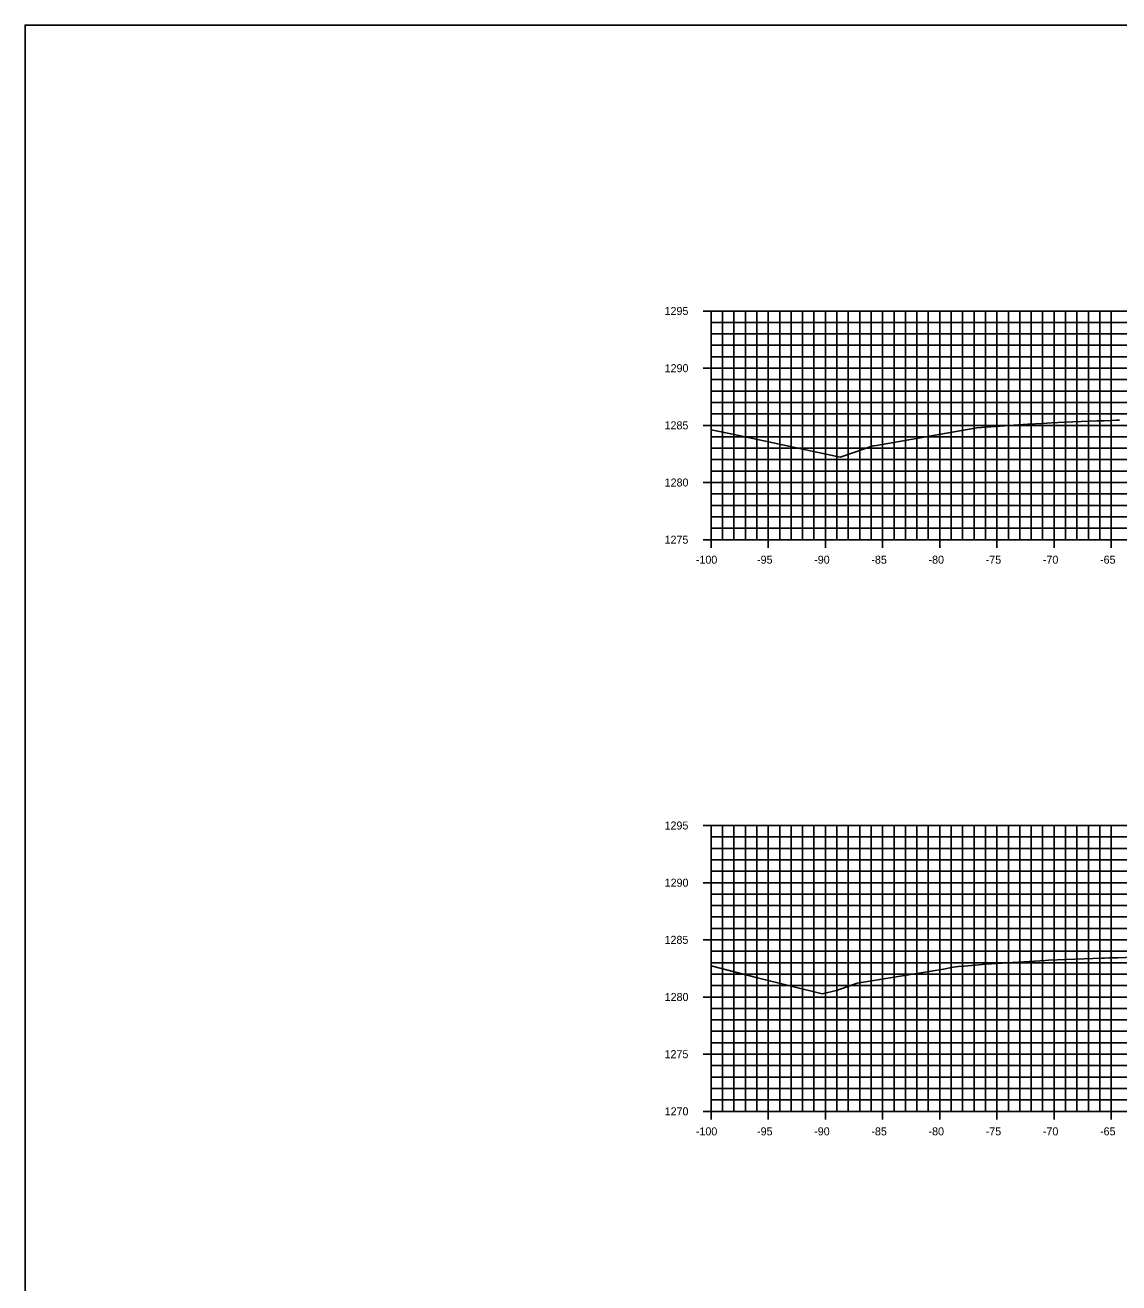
# Model space of a CAD drawing. Extents: x 674939 to 678919, y 750652 to 765176.
# Drawn here: x 678578.5 to 678674.2, y 757472.6 to 757582.6 of the extents above; entities that cross this region are included whole.
import ezdxf

# ---------------------------------------------------------------- set-up
doc = ezdxf.new("R2010")
doc.units = 0
for name, color, linetype in [('R_Axis', 7, 'Continuous'), ('R_Axis Annot', 7, 'Continuous'), ('R_Exist Surface', 7, 'Continuous'), ('R_Grid', 7, 'Continuous'), ('R_No Plot', 7, 'Continuous')]:
    doc.layers.add(name, color=color, linetype=linetype)

msp = doc.modelspace()

# ---------------------------------------------------------------- linework, layer by layer
at = {"layer": 'R_Axis'}
for p, q in [((678637.83, 757557.55), (678639.23, 757557.55)), ((678638.53, 757537.55), (678638.53, 757557.55)), ((678638.53, 757556.55), (678638.88, 757556.55)), ((678638.53, 757555.55), (678638.88, 757555.55)), ((678638.53, 757554.55), (678638.88, 757554.55)), ((678638.53, 757553.55), (678638.88, 757553.55)), ((678637.83, 757552.55), (678639.23, 757552.55)), ((678638.53, 757551.55), (678638.88, 757551.55)), ((678638.53, 757550.55), (678638.88, 757550.55)), ((678638.53, 757549.55), (678638.88, 757549.55)), ((678638.53, 757548.55), (678638.88, 757548.55)), ((678637.83, 757547.55), (678639.23, 757547.55)), ((678638.53, 757546.55), (678638.88, 757546.55)), ((678638.53, 757545.55), (678638.88, 757545.55)), ((678638.53, 757544.55), (678638.88, 757544.55)), ((678637.83, 757542.55), (678639.23, 757542.55)), ((678638.53, 757543.55), (678638.88, 757543.55)), ((678638.53, 757541.55), (678638.88, 757541.55)), ((678638.53, 757540.55), (678638.88, 757540.55)), ((678638.53, 757539.55), (678638.88, 757539.55)), ((678638.53, 757538.55), (678638.88, 757538.55)), ((678638.53, 757536.85), (678638.53, 757538.25)), ((678643.53, 757536.85), (678643.53, 757538.25)), ((678648.53, 757536.85), (678648.53, 757538.25)), ((678653.53, 757536.85), (678653.53, 757538.25)), ((678658.53, 757536.85), (678658.53, 757538.25)), ((678663.53, 757536.85), (678663.53, 757538.25)), ((678668.53, 757536.85), (678668.53, 757538.25)), ((678673.53, 757536.85), (678673.53, 757538.25)), ((678637.83, 757537.55), (678639.23, 757537.55)), ((678638.53, 757537.55), (678838.53, 757537.55)), ((678637.83, 757512.55), (678639.23, 757512.55)), ((678638.53, 757487.55), (678638.53, 757512.55)), ((678638.53, 757511.55), (678638.88, 757511.55)), ((678638.53, 757510.55), (678638.88, 757510.55)), ((678638.53, 757509.55), (678638.88, 757509.55)), ((678638.53, 757508.55), (678638.88, 757508.55)), ((678637.83, 757507.55), (678639.23, 757507.55)), ((678638.53, 757506.55), (678638.88, 757506.55)), ((678638.53, 757505.55), (678638.88, 757505.55)), ((678638.53, 757504.55), (678638.88, 757504.55)), ((678638.53, 757503.55), (678638.88, 757503.55)), ((678637.83, 757502.55), (678639.23, 757502.55)), ((678638.53, 757501.55), (678638.88, 757501.55)), ((678638.53, 757500.55), (678638.88, 757500.55)), ((678638.53, 757499.55), (678638.88, 757499.55)), ((678638.53, 757498.55), (678638.88, 757498.55)), ((678637.83, 757497.55), (678639.23, 757497.55)), ((678638.53, 757496.55), (678638.88, 757496.55)), ((678638.53, 757495.55), (678638.88, 757495.55)), ((678638.53, 757494.55), (678638.88, 757494.55)), ((678638.53, 757493.55), (678638.88, 757493.55)), ((678637.83, 757492.55), (678639.23, 757492.55)), ((678638.53, 757491.55), (678638.88, 757491.55)), ((678638.53, 757490.55), (678638.88, 757490.55)), ((678638.53, 757489.55), (678638.88, 757489.55)), ((678637.83, 757487.55), (678639.23, 757487.55)), ((678638.53, 757488.55), (678638.88, 757488.55)), ((678638.53, 757486.85), (678638.53, 757488.25)), ((678638.53, 757487.55), (678838.53, 757487.55)), ((678643.53, 757486.85), (678643.53, 757488.25)), ((678648.53, 757486.85), (678648.53, 757488.25)), ((678653.53, 757486.85), (678653.53, 757488.25)), ((678658.53, 757486.85), (678658.53, 757488.25)), ((678663.53, 757486.85), (678663.53, 757488.25)), ((678668.53, 757486.85), (678668.53, 757488.25)), ((678673.53, 757486.85), (678673.53, 757488.25))]:
    msp.add_line(p, q, dxfattribs=at)
at = {"layer": 'R_Exist Surface'}
for points in [[(678638.53, 757547.17), (678640.54, 757546.75), (678649.83, 757544.78), (678651.87, 757545.47), (678652.5, 757545.69), (678652.72, 757545.75), (678652.99, 757545.78), (678661.76, 757547.32), (678666.24, 757547.64), (678667.55, 757547.72), (678668.31, 757547.78), (678669.46, 757547.82), (678672.31, 757547.93), (678672.84, 757547.95), (678673.46, 757547.98), (678673.98, 757548), (678674.25, 757548.01)], [(678638.53, 757500.28), (678642.59, 757499.23), (678648.26, 757497.84), (678649.49, 757498.11), (678651.31, 757498.75), (678658.86, 757500), (678659.7, 757500.15), (678660.16, 757500.22), (678660.65, 757500.26), (678661, 757500.29), (678662.6, 757500.41), (678667.76, 757500.74), (678668.04, 757500.78), (678671.12, 757500.89), (678672.72, 757500.95), (678672.94, 757500.95), (678673.33, 757500.97), (678674.1, 757500.99), (678675.44, 757501.04)]]:
    msp.add_lwpolyline(points, dxfattribs=at)
at = {"layer": 'R_Grid'}
for p, q in [((678638.53, 757557.55), (678838.53, 757557.55)), ((678638.53, 757537.55), (678638.53, 757557.55)), ((678639.53, 757537.55), (678639.53, 757557.55)), ((678640.53, 757537.55), (678640.53, 757557.55)), ((678641.53, 757537.55), (678641.53, 757557.55)), ((678642.53, 757537.55), (678642.53, 757557.55)), ((678643.53, 757537.55), (678643.53, 757557.55)), ((678644.53, 757537.55), (678644.53, 757557.55)), ((678645.53, 757537.55), (678645.53, 757557.55)), ((678646.53, 757537.55), (678646.53, 757557.55)), ((678647.53, 757537.55), (678647.53, 757557.55)), ((678648.53, 757537.55), (678648.53, 757557.55)), ((678649.53, 757537.55), (678649.53, 757557.55)), ((678650.53, 757537.55), (678650.53, 757557.55)), ((678651.53, 757537.55), (678651.53, 757557.55)), ((678652.53, 757537.55), (678652.53, 757557.55)), ((678653.53, 757537.55), (678653.53, 757557.55)), ((678654.53, 757537.55), (678654.53, 757557.55)), ((678655.53, 757537.55), (678655.53, 757557.55)), ((678656.53, 757537.55), (678656.53, 757557.55)), ((678657.53, 757537.55), (678657.53, 757557.55)), ((678658.53, 757537.55), (678658.53, 757557.55)), ((678659.53, 757537.55), (678659.53, 757557.55)), ((678660.53, 757537.55), (678660.53, 757557.55)), ((678661.53, 757537.55), (678661.53, 757557.55)), ((678662.53, 757537.55), (678662.53, 757557.55)), ((678663.53, 757537.55), (678663.53, 757557.55)), ((678664.53, 757537.55), (678664.53, 757557.55)), ((678665.53, 757537.55), (678665.53, 757557.55)), ((678666.53, 757537.55), (678666.53, 757557.55)), ((678667.53, 757537.55), (678667.53, 757557.55)), ((678668.53, 757537.55), (678668.53, 757557.55)), ((678669.53, 757537.55), (678669.53, 757557.55)), ((678670.53, 757537.55), (678670.53, 757557.55)), ((678671.53, 757537.55), (678671.53, 757557.55)), ((678672.53, 757537.55), (678672.53, 757557.55)), ((678673.53, 757537.55), (678673.53, 757557.55)), ((678638.53, 757556.55), (678838.53, 757556.55)), ((678638.53, 757555.55), (678838.53, 757555.55)), ((678638.53, 757554.55), (678838.53, 757554.55)), ((678638.53, 757553.55), (678838.53, 757553.55)), ((678638.53, 757552.55), (678838.53, 757552.55)), ((678638.53, 757551.55), (678838.53, 757551.55)), ((678638.53, 757550.55), (678838.53, 757550.55)), ((678638.53, 757549.55), (678838.53, 757549.55)), ((678638.53, 757548.55), (678838.53, 757548.55)), ((678638.53, 757547.55), (678838.53, 757547.55)), ((678638.53, 757546.55), (678838.53, 757546.55)), ((678638.53, 757545.55), (678838.53, 757545.55)), ((678638.53, 757544.55), (678838.53, 757544.55)), ((678638.53, 757543.55), (678838.53, 757543.55)), ((678638.53, 757542.55), (678838.53, 757542.55)), ((678638.53, 757541.55), (678838.53, 757541.55)), ((678638.53, 757540.55), (678838.53, 757540.55)), ((678638.53, 757539.55), (678838.53, 757539.55)), ((678638.53, 757538.55), (678838.53, 757538.55)), ((678638.53, 757537.55), (678838.53, 757537.55)), ((678638.53, 757512.55), (678838.53, 757512.55)), ((678638.53, 757487.55), (678638.53, 757512.55)), ((678639.53, 757487.55), (678639.53, 757512.55)), ((678640.53, 757487.55), (678640.53, 757512.55)), ((678641.53, 757487.55), (678641.53, 757512.55)), ((678642.53, 757487.55), (678642.53, 757512.55)), ((678643.53, 757487.55), (678643.53, 757512.55)), ((678644.53, 757487.55), (678644.53, 757512.55)), ((678645.53, 757487.55), (678645.53, 757512.55)), ((678646.53, 757487.55), (678646.53, 757512.55)), ((678647.53, 757487.55), (678647.53, 757512.55)), ((678648.53, 757487.55), (678648.53, 757512.55)), ((678649.53, 757487.55), (678649.53, 757512.55)), ((678650.53, 757487.55), (678650.53, 757512.55)), ((678651.53, 757487.55), (678651.53, 757512.55)), ((678652.53, 757487.55), (678652.53, 757512.55)), ((678653.53, 757487.55), (678653.53, 757512.55)), ((678654.53, 757487.55), (678654.53, 757512.55)), ((678655.53, 757487.55), (678655.53, 757512.55)), ((678656.53, 757487.55), (678656.53, 757512.55)), ((678657.53, 757487.55), (678657.53, 757512.55)), ((678658.53, 757487.55), (678658.53, 757512.55)), ((678659.53, 757487.55), (678659.53, 757512.55)), ((678660.53, 757487.55), (678660.53, 757512.55)), ((678661.53, 757487.55), (678661.53, 757512.55)), ((678662.53, 757487.55), (678662.53, 757512.55)), ((678663.53, 757487.55), (678663.53, 757512.55)), ((678664.53, 757487.55), (678664.53, 757512.55)), ((678665.53, 757487.55), (678665.53, 757512.55)), ((678666.53, 757487.55), (678666.53, 757512.55)), ((678667.53, 757487.55), (678667.53, 757512.55)), ((678668.53, 757487.55), (678668.53, 757512.55)), ((678669.53, 757487.55), (678669.53, 757512.55)), ((678670.53, 757487.55), (678670.53, 757512.55)), ((678671.53, 757487.55), (678671.53, 757512.55)), ((678672.53, 757487.55), (678672.53, 757512.55)), ((678673.53, 757487.55), (678673.53, 757512.55)), ((678638.53, 757511.55), (678838.53, 757511.55)), ((678638.53, 757510.55), (678838.53, 757510.55)), ((678638.53, 757509.55), (678838.53, 757509.55)), ((678638.53, 757508.55), (678838.53, 757508.55)), ((678638.53, 757507.55), (678838.53, 757507.55)), ((678638.53, 757506.55), (678838.53, 757506.55)), ((678638.53, 757505.55), (678838.53, 757505.55)), ((678638.53, 757504.55), (678838.53, 757504.55)), ((678638.53, 757503.55), (678838.53, 757503.55)), ((678638.53, 757502.55), (678838.53, 757502.55)), ((678638.53, 757501.55), (678838.53, 757501.55)), ((678638.53, 757500.55), (678838.53, 757500.55)), ((678638.53, 757499.55), (678838.53, 757499.55)), ((678638.53, 757498.55), (678838.53, 757498.55)), ((678638.53, 757497.55), (678838.53, 757497.55)), ((678638.53, 757496.55), (678838.53, 757496.55)), ((678638.53, 757495.55), (678838.53, 757495.55)), ((678638.53, 757494.55), (678838.53, 757494.55)), ((678638.53, 757493.55), (678838.53, 757493.55)), ((678638.53, 757492.55), (678838.53, 757492.55)), ((678638.53, 757491.55), (678838.53, 757491.55)), ((678638.53, 757490.55), (678838.53, 757490.55)), ((678638.53, 757489.55), (678838.53, 757489.55)), ((678638.53, 757488.55), (678838.53, 757488.55)), ((678638.53, 757487.55), (678838.53, 757487.55))]:
    msp.add_line(p, q, dxfattribs=at)
at = {"layer": 'R_No Plot'}
msp.add_lwpolyline([(678578.53, 757362.55), (678918.53, 757362.55), (678918.53, 757582.55), (678578.53, 757582.55)], close=True, dxfattribs=at)

# ---------------------------------------------------------------- texts
at = {"layer": 'R_Axis Annot'}
for s, p in [('1295', (678634.46, 757557.2)), ('1290', (678634.47, 757552.2)), ('1285', (678634.46, 757547.2)), ('1280', (678634.47, 757542.2)), ('1275', (678634.46, 757537.2)), ('-100', (678637.2, 757535.45)), ('-95', (678642.55, 757535.45)), ('-90', (678647.55, 757535.45)), ('-85', (678652.55, 757535.45)), ('-80', (678657.55, 757535.45)), ('-75', (678662.55, 757535.45)), ('-70', (678667.55, 757535.45)), ('-65', (678672.55, 757535.45)), ('1295', (678634.46, 757512.2)), ('1290', (678634.47, 757507.2)), ('1285', (678634.46, 757502.2)), ('1280', (678634.47, 757497.2)), ('1275', (678634.46, 757492.2)), ('1270', (678634.47, 757487.2)), ('-100', (678637.2, 757485.45)), ('-95', (678642.55, 757485.45)), ('-90', (678647.55, 757485.45)), ('-85', (678652.55, 757485.45)), ('-80', (678657.55, 757485.45)), ('-75', (678662.55, 757485.45)), ('-70', (678667.55, 757485.45)), ('-65', (678672.55, 757485.45))]:
    msp.add_text(s, height=0.7, dxfattribs=at).set_placement(p)

doc.saveas('drawing.dxf')
